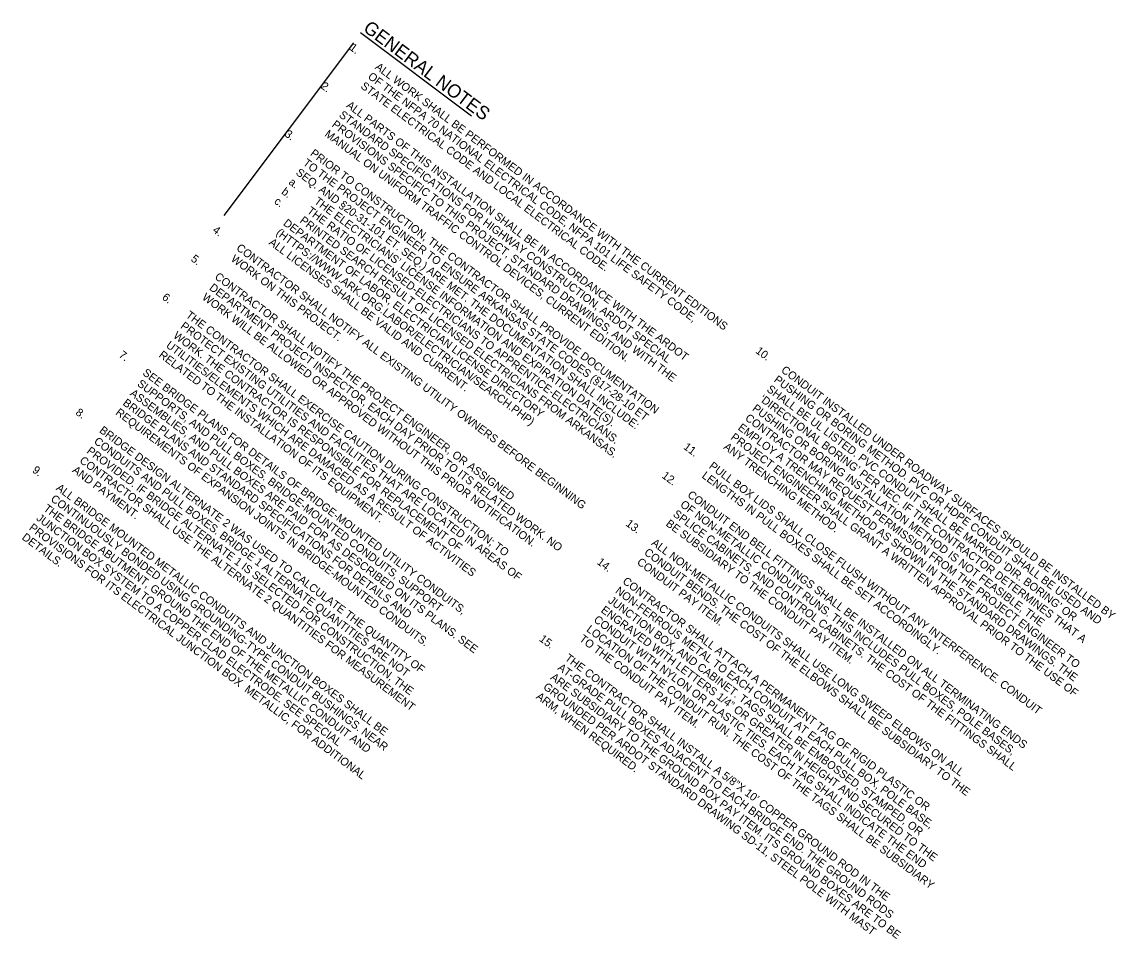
# Model space of a CAD drawing. Extents: x 626494 to 628584, y 365986 to 369269.
# Drawn here: x 627740.2 to 628232.4, y 368053.1 to 368465.6 of the extents above; entities that cross this region are included whole.
import ezdxf

# ---------------------------------------------------------------- set-up
doc = ezdxf.new("R2010")
doc.units = 0
doc.layers.add('R_Survey Control', color=7, linetype='Continuous')
doc.layers.add('USACE_Easement', color=7, linetype='Continuous')

msp = doc.modelspace()

# ---------------------------------------------------------------- linework, layer by layer
at = {"layer": 'R_Survey Control'}
msp.add_line((627889.46, 368456.25), (627831.09, 368378.53), dxfattribs=at)
at = {"layer": 'USACE_Easement'}
msp.add_line((627892.53, 368460.8), (627942.47, 368423.3), dxfattribs=at)

# ---------------------------------------------------------------- texts
for s, height, p in [('GENERAL NOTES', 6, (627893.35, 368461.86)), ('1.', 3.6, (627887.29, 368453.37)), ('ALL WORK SHALL BE PERFORMED IN ACCORDANCE WITH THE CURRENT EDITIONS ', 3.6, (627898.81, 368444.73)), ('OF THE NFPA 70 NATIONAL ELECTRICAL CODE, NFPA 101 LIFE SAFETY CODE, ', 3.6, (627895.57, 368440.41)), ('2.', 3.6, (627874.32, 368436.1)), ('STATE ELECTRICAL CODE AND LOCAL ELECTRICAL CODE.', 3.6, (627892.32, 368436.09)), ('ALL PARTS OF THIS INSTALLATION SHALL BE IN ACCORDANCE WITH THE ARDOT ', 3.6, (627885.84, 368427.46)), ('STANDARD SPECIFICATIONS FOR HIGHWAY CONSTRUCTION, ARDOT SPECIAL ', 3.6, (627882.6, 368423.14)), ('PROVISIONS SPECIFIC TO THIS PROJECT, STANDARD DRAWINGS, AND WITH THE ', 3.6, (627879.35, 368418.82)), ('3.', 3.6, (627858.11, 368414.51)), ('MANUAL ON UNIFORM TRAFFIC CONTROL DEVICES, CURRENT EDITION.', 3.6, (627876.11, 368414.5)), ('PRIOR TO CONSTRUCTION, THE CONTRACTOR SHALL PROVIDE DOCUMENTATION ', 3.6, (627869.63, 368405.86)), ('SEQ. AND §20-31-101 ET. SEQ.) ARE MET. THE DOCUMENTATION SHALL INCLUDE:', 3.6, (627863.14, 368397.23)), ('TO THE PROJECT ENGINEER TO ENSURE ARKANSAS STATE CODES (§17-28-10 ET ', 3.6, (627866.38, 368401.55)), ('a.', 3.6, (627859.9, 368392.91)), ('b.', 3.6, (627856.66, 368388.59)), ('c.', 3.6, (627853.41, 368384.27)), ('THE ELECTRICIANS’ LICENSE INFORMATION AND EXPIRATION DATE(S).', 3.6, (627871.41, 368384.26)), ('THE RATIO OF LICENSED-ELECTRICIANS TO APPRENTICE-ELECTRICIANS.', 3.6, (627868.17, 368379.95)), ('DEPARTMENT OF LABOR, ELECTRICIAN LICENSE DIRECTORY', 3.6, (627857.5, 368374.45)), ('PRINTED SEARCH RESULT OF LICENSED ELECTRICIANS FROM ARKANSAS.', 3.6, (627864.93, 368375.63)), ('4.       CONTRACTOR SHALL NOTIFY ALL EXISTING UTILITY OWNERS BEFORE BEGINNING ', 3.6, (627825.69, 368371.33)), ('(HTTPS://WWW.ARK.ORG.LABOR/ELECTRICIAN/SEARCH.PHP)', 3.6, (627854.26, 368370.14)), ('ALL LICENSES SHALL BE VALID AND CURRENT.', 3.6, (627851.01, 368365.82)), ('5.       CONTRACTOR SHALL NOTIFY THE PROJECT ENGINEER, OR ASSIGNED ', 3.6, (627815.96, 368358.38)), ('WORK ON THIS PROJECT.', 3.6, (627833.96, 368358.37)), ('DEPARTMENT PROJECT INSPECTOR, EACH DAY PRIOR TO ITS RELATED WORK. NO ', 3.6, (627824.23, 368345.41)), ('6.       THE CONTRACTOR SHALL EXERCISE CAUTION DURING CONSTRUCTION; TO ', 3.6, (627802.99, 368341.1)), ('WORK WILL BE ALLOWED OR APPROVED WITHOUT THIS PRIOR NOTIFICATION.', 3.6, (627820.99, 368341.09)), ('PROTECT EXISTING UTILITIES AND FACILITIES THAT ARE LOCATED IN AREAS OF ', 3.6, (627811.26, 368328.14)), ('WORK. THE CONTRACTOR IS RESPONSIBLE FOR REPLACEMENT OF ', 3.6, (627808.02, 368323.82)), ('UTILITIES/ELEMENTS WHICH ARE DAMAGED AS A RESULT OF ACTIVITIES ', 3.6, (627804.78, 368319.5)), ('7.       SEE BRIDGE PLANS FOR DETAILS OF BRIDGE-MOUNTED UTILITY CONDUITS, ', 3.6, (627783.53, 368315.19)), ('RELATED TO THE INSTALLATION OF ITS EQUIPMENT.', 3.6, (627801.53, 368315.18)), ('10.', 3.6, (628069.92, 368317.01)), ('PUSHING OR BORING METHOD. PVC OR HDPE CONDUIT SHALL BE USED AND ', 3.6, (628078.19, 368304.05)), ('CONDUIT INSTALLED UNDER ROADWAY SURFACES SHOULD BE INSTALLED BY ', 3.6, (628081.43, 368308.37)), ('SUPPORTS, AND PULL BOXES. BRIDGE-MOUNTED CONDUITS, SUPPORT ', 3.6, (627791.81, 368302.23)), ('SHALL BE UL LISTED. PVC CONDUIT SHALL BE MARKED ‘DIR. BORING’ OR ', 3.6, (628074.95, 368299.73)), ('BRIDGE PLANS AND STANDARD SPECIFICATIONS FOR DETAILS AND ', 3.6, (627785.32, 368293.59)), ('ASSEMBLIES, AND PULL BOXES ARE PAID FOR AS DESCRIBED ON ITS PLANS. SEE ', 3.6, (627788.56, 368297.91)), ('‘DIRECTIONAL BORING’ PER NEC. IF THE CONTRACTOR DETERMINES THAT A ', 3.6, (628071.7, 368295.41)), ('8.       BRIDGE DESIGN ALTERNATE 2 WAS USED TO CALCULATE THE QUANTITY OF ', 3.6, (627764.08, 368289.29)), ('REQUIREMENTS OF EXPANSION JOINTS IN BRIDGE-MOUNTED CONDUITS.', 3.6, (627782.08, 368289.28)), ('PUSHING OR BORING INSTALLATION METHOD IS NOT FEASIBLE, THE ', 3.6, (628068.46, 368291.09)), ('CONTRACTOR MAY REQUEST PERMISSION FROM THE PROJECT ENGINEER TO ', 3.6, (628065.22, 368286.78)), ('EMPLOY A TRENCHING METHOD AS SHOWN IN THE STANDARD DRAWINGS. THE ', 3.6, (628061.98, 368282.46)), ('CONDUITS AND PULL BOXES. BRIDGE 1 ALTERNATE QUANTITIES ARE NOT ', 3.6, (627772.35, 368276.32)), ('PROJECT ENGINEER SHALL GRANT A WRITTEN APPROVAL PRIOR TO THE USE OF ', 3.6, (628058.73, 368278.14)), ('PROVIDED. IF BRIDGE ALTERNATE 1 IS SELECTED FOR CONSTRUCTION, THE ', 3.6, (627769.11, 368272)), ('11.', 3.6, (628037.49, 368273.83)), ('ANY TRENCHING METHOD.', 3.6, (628055.49, 368273.82)), ('CONTRACTOR SHALL USE THE ALTERNATE 2 QUANTITIES FOR MEASUREMENT ', 3.6, (627765.87, 368267.68)), ('PULL BOX LIDS SHALL CLOSE FLUSH WITHOUT ANY INTERFERENCE. CONDUIT ', 3.6, (628049.01, 368265.19)), ('9.       ALL BRIDGE MOUNTED METALLIC CONDUITS AND JUNCTION BOXES SHALL BE ', 3.6, (627744.62, 368263.38)), ('AND PAYMENT. ', 3.6, (627762.62, 368263.37)), ('12.', 3.6, (628027.76, 368260.88)), ('LENGTHS IN PULL BOXES SHALL BE SET ACCORDINGLY. ', 3.6, (628045.76, 368260.87)), ('CONTINUOUSLY BONDED USING GROUNDING-TYPE CONDUIT BUSHINGS. NEAR ', 3.6, (627752.9, 368250.41)), ('CONDUIT END BELL FITTINGS SHALL BE INSTALLED ON ALL TERMINATING ENDS ', 3.6, (628039.28, 368252.23)), ('THE BRIDGE ABUTMENT, GROUND THE END OF THE METALLIC CONDUIT AND ', 3.6, (627749.65, 368246.09)), ('OF NON-METALLIC CONDUIT RUNS. THIS INCLUDES PULL BOXES, POLE BASES, ', 3.6, (628036.04, 368247.91)), ('JUNCTION BOX SYSTEM TO A COPPER CLAD ELECTRODE. SEE SPECIAL ', 3.6, (627746.41, 368241.78)), ('SPLICE CABINETS, AND CONTROL CABINETS. THE COST OF THE FITTINGS SHALL ', 3.6, (628032.79, 368243.6)), ('PROVISIONS FOR ITS ELECTRICAL JUNCTION BOX  METALLIC, FOR ADDITIONAL ', 3.6, (627743.17, 368237.46)), ('13.', 3.6, (628011.55, 368239.29)), ('BE SUBSIDIARY TO THE CONDUIT PAY ITEM. ', 3.6, (628029.55, 368239.28)), ('DETAILS.', 3.6, (627739.93, 368233.14)), ('ALL NON-METALLIC CONDUITS SHALL USE LONG SWEEP ELBOWS ON ALL ', 3.6, (628023.07, 368230.64)), ('CONDUIT BENDS. THE COST OF THE ELBOWS SHALL BE SUBSIDIARY TO THE ', 3.6, (628019.82, 368226.32)), ('14.', 3.6, (627998.58, 368222.02)), ('CONDUIT PAY ITEM.', 3.6, (628016.58, 368222)), ('CONTRACTOR SHALL ATTACH A PERMANENT TAG OF RIGID PLASTIC OR ', 3.6, (628010.1, 368213.37)), ('NON-FERROUS METAL TO EACH CONDUIT AT EACH PULL BOX, POLE BASE, ', 3.6, (628006.85, 368209.05)), ('ENGRAVED WITH LETTERS 1/4” OR GREATER IN HEIGHT AND SECURED TO THE ', 3.6, (628000.37, 368200.41)), ('JUNCTION BOX, AND CABINET. TAGS SHALL BE EMBOSSED, STAMPED, OR ', 3.6, (628003.61, 368204.73)), ('CONDUIT WITH NYLON OR PLASTIC TIES. EACH TAG SHALL INDICATE THE END ', 3.6, (627997.13, 368196.1)), ('LOCATION OF THE CONDUIT RUN. THE COST OF THE TAGS SHALL BE SUBSIDIARY ', 3.6, (627993.88, 368191.78)), ('15.', 3.6, (627972.64, 368187.47)), ('TO THE CONDUIT PAY ITEM.', 3.6, (627990.64, 368187.46)), ('THE CONTRACTOR SHALL INSTALL A 5/8”X 10’ COPPER GROUND ROD IN THE ', 3.6, (627984.16, 368178.82)), ('AT-GRADE PULL BOXES ADJACENT TO EACH BRIDGE END. THE GROUND RODS ', 3.6, (627980.91, 368174.51)), ('ARE SUBSIDIARY TO THE GROUND BOX PAY ITEM. ITS GROUND BOXES ARE TO BE ', 3.6, (627977.67, 368170.19)), ('ARM, WHEN REQUIRED. ', 3.6, (627971.19, 368161.55)), ('GROUNDED PER ARDOT STANDARD DRAWING SD-11, STEEL POLE WITH MAST ', 3.6, (627974.43, 368165.87))]:
    msp.add_text(s, height=height, rotation=323.0968, dxfattribs=at).set_placement(p)

doc.saveas('drawing.dxf')
